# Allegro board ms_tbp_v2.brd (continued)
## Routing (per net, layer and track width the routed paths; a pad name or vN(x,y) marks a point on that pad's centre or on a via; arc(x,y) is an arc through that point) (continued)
SAS_B2_TX7P: length 15.2
  LYR6 w0.112: J23.G5 387.78,13.07 arc(387.92,13.42) 388.27,13.56 388.41,13.56 arc(388.78,13.72) 388.93,14.08 388.93,17.99 arc(388.96,18.06) 389.03,18.08 arc(389.12,18.12) 389.16,18.22 389.16,18.64 arc(389.12,18.75) 389.01,18.79 arc(388.95,18.82) 388.93,18.87 388.93,19.44 388.97,19.48 388.97,19.95 388.93,19.99 388.93,20.47 arc(388.86,20.81) 388.67,21.09 387.38,22.39 arc(387.2,22.65) 387.14,22.96 387.14,23.1 arc(387.05,23.55) 386.8,23.93 386.58,24.14 arc(386.36,24.48) 386.28,24.88 386.28,24.9 arc(386.3,25.03) 386.37,25.14 386.66,25.42 arc(386.67,25.43) 386.68,25.44 386.72,25.46 arc(386.8,25.47) 386.87,25.41 J24.2D7
SAS_B2_TX8N: length 22.5
  LYR6 w0.112: J24.2C8 386.6,29.71 arc(386.61,29.63) 386.56,29.56 386.09,29.09 arc(385.84,28.93) 385.55,28.87 385.16,28.87 arc(384.56,28.62) 384.31,28.02 384.31,26.84 384.31,22.5 arc(384.46,21.73) 384.9,21.08 386.15,19.83 arc(386.48,19.33) 386.6,18.75 386.6,17.09 386.6,11.21 arc(386.54,11.07) 386.39,11.01 386.31,11.01 arc(385.93,11.17) J23.F6
SAS_B2_TX8P: length 23
  LYR6 w0.112: J24.2C7 386.87,29.21 arc(386.8,29.27) 386.72,29.26 386.73,29.25 386.33,28.85 arc(385.97,28.61) 385.55,28.52 385.16,28.52 arc(384.8,28.38) 384.65,28.02 384.65,26.84 384.65,22.5 arc(384.78,21.86) 385.14,21.32 386.39,20.07 arc(386.8,19.47) 386.94,18.75 386.94,18.11 386.98,18.06 386.98,17.61 386.94,17.56 386.94,17.09 arc(386.97,17.02) 387.04,16.99 arc(387.13,16.95) 387.17,16.86 387.17,16.49 arc(387.12,16.38) 387.02,16.34 arc(386.96,16.32) 386.94,16.26 386.94,11.21 arc(386.78,10.83) 386.39,10.67 386.26,10.67 arc(386.14,10.64) 386.03,10.57 385.91,10.45 arc(385.81,10.31) J23.E6
SERIAL_B1_RX1: length 221.1
  TOP w0.102: v1(163.97,18.69) 164.14,18.86 168.68,18.86 169.93,17.61 169.93,6.89 J11.B3 ; U1.S2 7.3,45.76 10.6,42.45 10.6,35.27 10.06,34.73 10.06,34.2 10.29,33.97 v1(11.41,33.97)
  LYR3 w0.13: v1(53.65,31.2) 53.25,31.2 49.55,34.89 13.78,34.89 12.86,33.97 v1(11.41,33.97)
  BOTTOM w0.102: J7.G3 125.33,13.95 125.33,16.32 125,16.65 125,18.78 126.4,20.18 ; 126.4,20.18 126.4,20.92 125.74,21.58 120.12,21.58 116.29,25.41 101.33,25.41 100.23,26.51 100.23,26.51 99.62,27.12 95.57,27.12 95.08,26.63 86.32,26.63 80.25,32.7 56.47,32.7 54.97,31.2 v1(53.65,31.2) ; 126.4,20.18 128.3,20.18 130.74,22.62 130.74,26.25 131.78,27.29 133.46,27.29 135.77,24.98 143.72,24.98 146.01,22.69 157.03,22.69 158.94,20.79 158.94,17.2 159.75,16.38 161.66,16.38 v1(163.97,18.69)
SERIAL_B1_RX2: length 172.7
  TOP w0.102: U1.S6 2.22,47.59 6.64,43.17 6.64,42.86 9.35,40.15 9.35,35.6 8.94,35.19 8.94,32.63 9.73,31.84 11.36,31.84 v1(11.39,31.81) ; v1(123.73,20.84) 121.5,18.61 121.5,13.86 122.41,12.94 J7.G4
  LYR3 w0.13: v1(11.39,31.81) 12.67,31.81 14.62,33.77 37.98,33.77 41.92,29.83 51.77,29.83 52.48,29.12 v1(53.63,29.12)
  LYR4 w0.13: J1.I8 14.89,16.95 14.89,24.96 11.39,28.46 v1(11.39,31.81)
  BOTTOM w0.102: v1(123.73,20.84) 118.93,20.84 115.88,23.89 89.72,23.89 88.88,24.73 86.49,24.73 79.76,31.46 57.72,31.46 55.38,29.12 v1(53.63,29.12)
SERIAL_B1_TX1: length 220
  TOP w0.102: U1.S1 8.57,45.12 10.9,42.79 10.9,35.16 10.57,34.84 v1(10.57,34.48) ; J11.A3 170.73,4.64 169.62,5.75 169.62,17.45 169.59,17.48 168.83,18.24 163.37,18.24 v1(162.84,18.77) ; v1(127.82,20.76) 127.52,20.76 123.81,17.06 123.81,15.05 J7.H3
  LYR3 w0.13: v1(54.39,31.76) 53.32,31.76 49.91,35.18 13.5,35.18 12.81,34.48 v1(10.57,34.48)
  BOTTOM w0.102: v1(162.84,18.77) 160.77,16.7 159.82,16.7 159.3,17.22 159.3,20.93 157.16,23.08 146.13,23.08 143.85,25.36 136.02,25.36 133.76,27.62 131.68,27.62 130.36,26.3 130.36,22.75 129.39,21.78 128.84,21.78 v1(127.82,20.76) 126.75,21.83 120.27,21.83 116.44,25.67 101.48,25.67 99.76,27.38 95.19,27.38 94.82,27.01 89.85,27.01 89.72,26.89 86.44,26.89 80.3,33.03 56.37,33.03 55.1,31.76 v1(54.39,31.76)
SERIAL_B1_TX2: length 197.5
  TOP w0.102: v1(10.57,32.37) 9.81,32.37 9.23,32.96 9.23,35.1 9.65,35.52 9.65,40.41 7.78,42.28 7.78,43.4 3.49,47.69 U1.S5 ; J7.H4 122.42,14.35 123.27,15.2 123.27,17.31 125.2,19.24 v1(125.2,20.89)
  LYR3 w0.13: v1(10.57,32.37) 12.73,32.37 14.41,34.05 38.82,34.05 41.74,31.13 51.29,31.13 52.81,29.6 v1(54.41,29.6)
  LYR4 w0.13: J1.H8 15.02,13.46 15.02,3.87 14.65,3.51 13.39,3.51 13.11,3.78 13.11,25.74 9.56,29.3 9.56,31.94 9.99,32.37 v1(10.57,32.37)
  BOTTOM w0.102: v1(125.2,20.89) 124.56,20.89 124.32,21.31 118.89,21.31 115.96,24.24 89.8,24.24 88.68,25.36 86.32,25.36 79.92,31.76 57.51,31.76 55.35,29.6 v1(54.41,29.6)
SERIAL_B2_RX1: length 467.6
  TOP w0.102: J23.B3 390.93,6.89 390.93,17.61 389.85,18.69 384.68,18.69 v1(384.13,19.24)
  LYR3 w0.13: v1(7.3,42.99) 7.73,42.99 9.3,41.41 9.3,40.83 13.55,36.59 51.5,36.59 v1(53.78,34.3)
  BOTTOM w0.102: 346.31,19.9 346.31,13.24 346.11,13.04 J19.G3 ; 346.31,19.9 346.31,20.6 345.27,21.64 342.71,21.64 340.51,23.84 321.7,23.84 318.35,27.18 316.12,27.18 315.78,27.52 314.13,27.52 313.75,27.14 312.15,27.14 311.51,27.77 311.51,46.95 306.23,52.24 268.08,52.24 267.34,52.97 97.13,52.97 79.33,35.17 55.89,35.17 54.97,34.25 53.83,34.25 v1(53.78,34.3) ; 346.31,19.9 346.92,19.29 351.24,19.29 351.98,20.03 351.98,26.5 352.71,27.24 354.01,27.24 356.27,24.98 364.01,24.98 366.35,22.64 377.53,22.64 379.56,20.61 379.56,16.55 380.58,15.53 382.33,15.53 384.49,17.69 384.49,18.45 384.13,18.81 v1(384.13,19.24) ; v1(7.3,42.99) U1.S11
SERIAL_B2_RX2: length 523.9
  TOP w0.102: J19.G4 342.45,13.91 342.45,15.94 340.77,17.61 v1(340.77,21.17)
  LYR3 w0.13: v1(2.22,43.07) 3.75,41.53 6.85,41.53 12.92,35.46 50.11,35.46 53.25,32.32 v1(53.7,32.32)
  LYR6 w0.13: v1(340.77,21.17) 339.61,21.17 338.11,22.67 334.59,22.67 327.74,15.83 323.14,15.83 318.9,11.59 318.9,8.13 319.3,7.74 319.3,5.62 317.12,3.44 274.76,3.44 273.84,4.36 v1(272.3,4.36)
  BOTTOM w0.102: J13.I8 237.04,15.84 237.85,15.02 237.85,4.1 238.27,3.68 262.33,3.68 264.45,5.8 267.72,5.8 269.17,4.36 v1(272.3,4.36) ; v1(340.77,21.17) 340.29,21.17 338.82,22.64 328.73,22.64 328.43,22.34 311.67,22.34 305.8,28.21 305.8,29.53 306.18,29.91 306.18,46.6 303.68,49.1 268.83,49.1 265.97,51.96 97.75,51.96 85.78,39.98 85.78,38.93 80.23,33.37 56.1,33.37 55.05,32.32 v1(53.7,32.32) ; v1(2.22,43.07) U1.S7
SERIAL_B2_TX1: length 464.9
  TOP w0.102: v1(383.75,18.24) 383.86,18.35 389.72,18.35 390.12,17.95 390.62,17.45 390.62,5.8 J23.A3
  LYR3 w0.13: v1(347.17,21.17) 347.17,20.64 344.69,18.15 344.69,15.17 J19.H3 ; v1(8.57,42.96) 9.63,41.9 9.63,40.91 13.67,36.87 51.87,36.87 53.96,34.79 v1(54.49,34.79)
  BOTTOM w0.102: v1(8.57,42.96) U1.S12 ; v1(54.49,34.79) 54.54,34.73 54.8,34.73 55.48,35.42 79.15,35.42 96.96,53.23 267.6,53.23 268.28,52.54 306.61,52.54 311.92,47.23 311.92,27.88 312.4,27.39 313.24,27.39 313.75,27.9 315.78,27.9 316.16,27.52 318.75,27.52 322.13,24.14 340.7,24.14 342.92,21.92 346.35,21.92 347.1,21.17 v1(347.17,21.17) 347.17,21.15 348.55,19.77 351.09,19.77 351.62,20.31 351.62,26.73 352.61,27.72 354.11,27.72 356.32,25.51 364.42,25.51 366.81,23.13 378.09,23.13 380.19,21.02 380.19,16.95 380.73,16.42 381.93,16.42 v1(383.75,18.24)
SERIAL_B2_TX2: length 523.6
  TOP w0.102: J19.H4 343.75,14.34 344.41,15 344.41,18.83 v1(342.07,21.17)
  LYR3 w0.13: v1(54.46,32.8) 53.27,32.8 50.33,35.74 13.15,35.74 7.04,41.85 4.68,41.85 v1(3.49,43.04)
  LYR6 w0.13: J13.H8 238.01,13.43 238.01,4.09 238.48,3.62 262.55,3.62 264.57,5.63 273.53,5.63 275.19,3.98 317.17,3.98 318.92,5.73 318.92,7.21 318.43,7.71 318.43,11.69 320.14,13.41 320.14,13.81 322.7,16.37 327.64,16.37 334.42,23.15 339.71,23.15 341.69,21.17 v1(342.07,21.17)
  BOTTOM w0.102: v1(54.46,32.8) 54.49,32.83 55.05,32.83 55.87,33.65 80,33.65 85.5,39.15 85.5,40.11 97.6,52.21 266.25,52.21 267.77,50.69 303.82,50.69 307.7,46.8 307.7,42.41 306.84,41.54 306.84,29.88 307.6,29.12 307.6,28.49 307.93,28.16 307.93,27.27 312.55,22.65 328,22.65 328.38,23.03 339.91,23.03 341.76,21.17 v1(342.07,21.17) ; U1.S8 v1(3.49,43.04)
SKU_B1_ID0: length 35.9
  TOP w0.102: v1(124.65,40.22) R3.1 R2.2
  LYR3 w0.13: J7.F3 124.42,11.65 125.28,12.51 125.28,16.01 124.75,16.55 124.75,19.57 126.12,20.94 126.12,23.67 128.28,25.83 128.28,34.99 125.38,37.88 124.18,37.88 123.8,38.27 123.8,39.37 v1(124.65,40.22)
SKU_B1_ID1: length 33.1
  TOP w0.102: v1(123.04,41.16) 123.02,41.14 R5.1 R4.2
  LYR3 w0.13: J7.I4 122.42,16.1 123.15,16.83 123.15,18.35 120.58,20.92 120.58,24.27 118.57,26.28 118.57,34.53 121.27,37.22 122.97,37.22 123.49,37.75 123.49,40.71 v1(123.04,41.16)
SKU_B1_ID2: length 58.8
  TOP w0.102: R75.1 R6.2 R7.1 91.64,28.65 v1(91.65,28.64)
  LYR3 w0.13: v1(129.29,23.81) 129.95,23.15 129.95,21.78 129.12,20.94 129.12,19.37 127.44,17.69 127.44,12.51 126.47,11.54 J7.F2
  BOTTOM w0.102: v1(129.29,23.81) 127.88,22.4 120.58,22.4 116.75,26.23 101.94,26.23 100.21,27.95 92.79,27.95 92.11,28.64 v1(91.65,28.64)
SKU_B2_ID0: length 39
  TOP w0.102: R31.1 R30.2 343.03,43.62 v1(343.87,43.62)
  LYR3 w0.13: J19.F3 345.42,11.65 346.21,12.44 346.21,18.63 347.96,20.38 347.96,24.45 349.74,26.23 349.74,34.33 345.93,38.14 344.89,38.14 344.63,38.4 344.63,42.87 v1(343.87,43.62)
SKU_B2_ID1: length 32.4
  TOP w0.102: v1(344.1,40.75) R33.1 R32.2
  LYR3 w0.13: J19.I4 344.18,16.5 344.18,21.17 339.61,25.74 339.61,33.69 342.73,36.82 343.64,36.82 344.43,37.6 344.43,38.16 344.1,38.49 v1(344.1,40.75)
SKU_B2_ID2: length 55.8
  TOP w0.102: R61.1 R34.2 R35.1 v1(313.27,29.78)
  LYR3 w0.13: J19.F2 348.6,12.72 348.6,16.07 350.76,18.22 v1(350.76,21.12)
  BOTTOM w0.102: v1(350.76,21.12) 350.07,21.81 348.67,21.81 348.02,22.46 343.24,22.46 340.8,24.9 322.66,24.9 317.79,29.78 v1(313.27,29.78)
UNNAMED_4_1X2HDR_I81_IO: length 3.4
  TOP w0.305: R9.1 89.44,45.72 J25.2
UNNAMED_4_1X2HDR_I90_IO: length 3.7
  TOP w0.305: J26.2 81.62,45.93 R11.1
UNNAMED_4_FERRITE_I148_A: length 1.5
  TOP w0.305: FB1.1 v1(136.79,4.28) 136.76,4.31 FS1.2
UNNAMED_4_FERRITE_I151_B: length 1.8
  TOP w0.305: FB2.2 144.16,4.37 v1(144.18,4.38) 144.2,4.36 FS2.1
UNNAMED_6_1X2HDR_I52_IO: length 3.4
  TOP w0.305: R37.1 310.44,45.72 J28.2
UNNAMED_6_1X2HDR_I56_IO: length 3.7
  TOP w0.305: J29.2 298.92,45.94 R39.1
UNNAMED_6_FERRITE_I24_A: length 1.6
  TOP w0.305: FB3.1 v1(357.74,4.28) FS3.2
UNNAMED_6_FERRITE_I27_B: length 1.8
  TOP w0.305: 365.21,4.31 FS4.1 ; 365.21,4.31 364.37,4.31 FB4.2 ; 365.21,4.31 v1(365.21,4.33)
UNNAMED_8_FERRITE_I47_B: length 1.4
  TOP w0.305: 376.79,38.94 377.46,38.94 FS7.1 ; 376.79,38.94 v1(376.79,38.95) ; 376.79,38.94 FB7.2
UNNAMED_8_FERRITE_I51_A: length 1.4
  TOP w0.305: FS5.2 377.66,43.1 v1(377.67,43.09) FB5.1
UNNAMED_8_FERRITE_I54_A: length 1.4
  TOP w0.305: FS6.2 377.96,50.25 377.96,49.57 v1(377.98,49.54) 377.96,49.52 FB6.1
UNNAMED_16_FERRITE_I40_A: length 1.4
  TOP w0.381: FS9.2 156.47,49.34 v1(156.45,49.31) 156.47,49.29 FB9.1
UNNAMED_16_FERRITE_I46_B: length 1.6
  TOP w0.305: FB10.2 155.44,38.81 v1(155.46,38.8) 155.48,38.83 FS10.1
UNNAMED_16_FERRITE_I115_A: length 1.6
  TOP w0.305: FB8.1 156.47,43.3 v1(156.45,43.32) FS8.2
USB_B1_N: length 25
  BOTTOM w0.127: J1.C10 11.45,6.89 10.83,6.89 10.52,7.2 10.52,7.43 10.11,7.84 9.89,7.84 9.61,8.12 9.61,8.87 9.79,9.05 9.79,9.58 9.61,9.76 9.61,10.02 7.25,12.38 7.25,13.61 7.42,13.79 7.42,14.22 7.25,14.4 7.25,14.87 6.16,15.96 6.16,16.19 5.83,16.52 5.6,16.52 5.19,16.93 4.9,16.93 4.72,17.11 4.34,17.11 4.16,16.93 3.66,16.93 3.49,17.11 3.06,17.11 2.88,16.93 2.65,16.93 1.4,18.17 1.4,20.23 1.58,20.41 1.58,20.89 1.4,21.07 1.4,21.3 2.09,21.99 2.77,21.99 U2.2
USB_B1_P: length 25
  BOTTOM w0.127: U2.3 2.77,22.29 1.97,22.29 1.1,21.42 1.1,18.05 2.52,16.62 5.06,16.62 6.94,14.74 6.94,12.26 9.3,9.89 9.3,7.99 10.71,6.59 11.45,6.59 J1.B10
USB_B2_N: length 23.9
  BOTTOM w0.127: U3.2 220.01,11.74 219.17,11.74 218.19,10.76 218.19,10.53 218.37,10.35 218.37,9.92 218.19,9.74 218.19,9.31 218.37,9.13 218.37,8.7 218.19,8.52 218.19,7.43 218.45,7.17 218.68,7.17 218.99,6.86 218.99,6.63 219.77,5.85 220.11,5.85 220.29,6.03 220.72,6.03 220.9,5.85 221.33,5.85 221.51,6.03 221.94,6.03 222.12,5.85 222.55,5.85 222.73,6.03 223.16,6.03 223.34,5.85 223.77,5.85 223.95,6.03 224.38,6.03 224.56,5.85 228.61,5.85 229.65,6.89 232.45,6.89 J13.C10
USB_B2_P: length 23.9
  BOTTOM w0.127: U3.3 220.01,12.04 219.05,12.04 217.89,10.88 217.89,7.3 219.64,5.55 228.73,5.55 229.77,6.59 232.45,6.59 J13.B10

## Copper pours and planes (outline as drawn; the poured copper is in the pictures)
GND on TOP: 252.61,11.81 260.93,10.64 252.61,9.48
GND on TOP: 318.7,3.22 318.43,3.32 318.14,3.35 274.38,3.35 274.38,34.38 273.36,35.39 240.34,35.39 231.96,27.01 231.96,4.41 230.91,3.35 147.47,3.35 147.47,5 147.45,5.02 143.19,5.02 143.19,8.72 137.47,8.72 137.47,4.9 133.78,4.9 133.78,3.35 117.39,3.35 117.39,15.98 114.91,15.98 114.91,15.96 111.11,15.96 111.11,16.89 111.1,16.9 108.14,16.9 108.14,15.96 95.82,15.96 95.82,23.71 90.61,28.92 87.9,28.92 86.8,30.02 86.8,54.03 423.84,54.03 425.39,53.39 426.03,51.84 426.03,15.5 426.36,14.63 427.19,14.2 427.19,5.54 426.55,3.99 425,3.35 398.11,3.35 397.57,3.9 397.57,16.22 395.66,18.12 384.87,18.12 383.73,16.98 383.73,3.99 383.09,3.35 338.13,3.35 338.13,16.09 325.12,16.09 325.12,16.87 324.15,17.83 323.88,17.83 323.58,17.54 323.58,17.12 323.59,17.12 323.59,16.09 318.7,16.09 ; 8 cut-outs
GND on TOP: 31.48,44.96 31.48,54.35 31.49,54.34 51.05,54.34 51.05,44.35 50.63,43.93 32.5,43.93
GND on BOTTOM: 94.98,22.44 94.98,3.14 52.69,3.14 52.69,27.39 53.58,28.28 56.07,28.28 58.76,30.98 79.38,30.98 87.1,23.25 94.17,23.25
GND on BOTTOM: 31.48,54.29 31.48,44.82 32.19,44.11 50.73,44.11 51.04,44.41 51.04,54.29
GND on BOTTOM: 316.87,53.89 316.87,30.82 316.95,30.82 317.43,30.34 318.65,30.34 323.17,25.82 350.27,25.82 350.4,25.95 350.4,27.67 352.3,29.58 354.31,29.58 356.75,27.14 369.2,27.14 369.2,53.89
GND on LYR2: 98.19,0.56 98.19,2.04 97.88,2.79 97.13,3.1 1.5,3.1 0.83,3.37 0.56,4.04 0.56,54.11 0.8,54.35 9.65,54.35 9.89,54.11 9.89,45.19 10.8,44.28 11.71,45.19 11.71,54.11 11.94,54.34 51.29,54.34 51.52,54.11 51.52,46.34 52.12,44.88 53.58,44.28 54.58,44.28 56.04,44.88 56.64,46.34 56.64,52.34 57.21,53.71 58.58,54.28 423.84,54.28 425.57,53.57 426.28,51.84 426.28,15.5 426.59,14.75 427.34,14.44 427.44,14.44 427.44,5.54 426.73,3.81 425,3.1 337.28,3.1 336.54,2.79 336.23,2.04 336.23,0.56 319.19,0.56 319.19,2.04 318.88,2.79 318.13,3.1 192.64,3.1 192.59,3.05 115.92,3.05 115.9,3.03 115.41,2.64 115.23,2.04 115.23,0.56
GND on LYR3: 161.6,3.52 161.6,54.18 161.61,54.19 305.87,54.19 305.87,28.03 309.94,23.96 313.88,23.96 315.27,22.57 315.27,4.03 302.19,4.03 302.06,3.9 274,3.9 274,31.97 269.78,36.18 269.78,36.21 240.8,36.21 239.99,35.39 239.99,35.37 230.94,26.33 230.94,3.52
GND on LYR4: 381.41,3.14 381.41,53.81 384.52,53.81 384.55,53.78 406.53,53.78 406.53,3.14
GND on LYR5: 317.28,3.11 317.28,23.91 317.35,23.91 317.23,24.04 317.23,53.81 424.75,53.81 426.14,52.41 426.14,14.82 427.29,13.68 427.29,4.79 426.09,3.59 420.55,3.14 336.91,3.14 336.24,2.46 336.24,2.4 334.4,0.56 321.54,0.56 318.98,3.12
GND on LYR5: 272.73,30.8 264.45,30.8 264.22,30.57 264.22,28.92 263.96,28.66 262.95,28.66 258.2,33.41 240.98,33.41 233.84,26.28 233.84,4.41 234.4,3.85 272.24,3.85 272.73,4.33
GND on LYR5: 13.16,33.69 48.34,33.69 49.69,32.35 50.78,32.35 52.2,30.92 52.2,4 51.86,3.66 41.5,3.66 41.49,3.64 13.6,3.64 13.55,3.59 9.63,3.59 9.51,3.72 9.51,11.87 7.83,13.55 1.66,13.55 1.66,27.75 1.89,27.98 6.08,27.98 6.1,28 7.47,28
GND on LYR5: 97.9,3.01 97.9,11.04 103.78,16.92 108.7,16.92 111.88,20.09 116.34,20.09 118.55,22.3 159.95,22.3 159.97,37.06 159.97,37.63 161.66,39.33 162.24,39.91 182.99,39.91 184.44,38.47 184.44,38.49 185.05,37.88 185.05,3.16 185.02,3.19 160,3.19 160,22.29 130.84,22.29 130.84,3.24 159.57,3.24 159.57,3.19 115.81,3.19 113.18,0.56 100.35,0.56
GND on LYR7: 98.19,0.56 98.19,2.04 97.88,2.79 97.13,3.1 1.5,3.1 0.83,3.37 0.56,4.04 0.56,54.11 0.79,54.34 9.66,54.34 9.89,54.11 9.89,45.19 10.8,44.28 11.71,45.19 11.71,54.11 11.94,54.34 51.29,54.34 51.52,54.11 51.52,46.34 52.12,44.88 53.58,44.28 54.58,44.28 56.04,44.88 56.64,46.34 56.64,52.34 57.21,53.71 58.58,54.28 423.84,54.28 425.57,53.57 426.28,51.84 426.28,15.5 426.59,14.75 427.34,14.44 427.44,14.44 427.44,5.54 426.73,3.81 425,3.1 337.28,3.1 336.54,2.79 336.23,2.04 336.23,0.56 319.19,0.56 319.19,2.04 318.88,2.79 318.13,3.1 192.64,3.1 192.59,3.05 115.92,3.05 115.9,3.03 115.41,2.64 115.23,2.04 115.23,0.56
P3V3_10G_B1_VCCR on TOP (solid shape): 140.05,7.99 140.05,5.43 138.97,5.43 138.98,4.79 138.72,4.53 138.72,4.03 138.04,4.03 138.04,8.3 139.74,8.3
P3V3_10G_B1_VCCR on TOP: 139.26,13.83 139.77,13.83 139.77,17.37 139.61,17.53 139.17,17.53 139,17.36 139,16.11 139.26,15.84
P3V3_10G_B1_VCCT on TOP (solid shape): 142.65,4.03 141.9,4.03 141.9,4.79 141.26,5.42 140.64,5.42 140.64,7.98 140.95,8.29 142.65,8.29
P3V3_10G_B1_VCCT on TOP: 140.55,13.84 140.05,13.84 140.05,17.38 140.21,17.54 140.59,17.54 140.77,17.36 140.77,16.07 140.55,15.85
P3V3_10G_B2_VCCR on TOP (solid shape): 361.05,7.99 361.05,5.43 359.97,5.43 359.98,4.79 359.72,4.53 359.72,4.03 359.04,4.03 359.04,8.3 360.74,8.3
P3V3_10G_B2_VCCR on TOP: 360.26,13.83 360.76,13.83 360.76,17.38 360.61,17.53 360.14,17.53 360,17.39 360,16.11 360.26,15.85
P3V3_10G_B2_VCCT on TOP (solid shape): 363.65,4.03 362.9,4.03 362.9,4.79 362.26,5.42 361.64,5.42 361.64,7.98 361.95,8.29 363.65,8.29
P3V3_10G_B2_VCCT on TOP: 361.56,13.83 361.06,13.83 361.06,17.38 361.22,17.54 361.58,17.54 361.8,17.31 361.8,16.09 361.56,15.85
P3V3_40G_B1_VCC1 on TOP: 151.95,36.92 153.6,36.92 154.13,37.45 154.13,37.88 154.44,38.19 155.15,38.19 155.33,38.01 155.33,35.27 155.05,34.99 152.43,34.99 151.95,35.47
P3V3_40G_B1_VCC_RX on TOP: 106.19,8.66 105.83,8.66 105.83,10.61 105.54,10.9 105.54,11.16 105.77,11.39 106.26,11.39 106.26,10.69 106.19,10.63
P3V3_40G_B1_VCC_RX on TOP: 152.29,50.09 154.49,50.09 155.09,49.49 155.51,49.49 155.87,49.12 155.87,48.16 156,48.03 156,47.05 154.77,47.05 154.58,47.24 152.2,47.24 152.08,47.37 152.08,49.87
P3V3_40G_B1_VCC_TX on TOP: 152.2,43.99 154.11,43.99 155.3,42.8 155.85,42.8 155.85,42.06 155.98,41.94 155.98,40.96 154.74,40.96 154.55,41.15 152.2,41.15 152.05,41.3 152.05,43.84
P3V3_40G_B2_VCC1 on TOP: 373.33,37.05 374.98,37.05 375.52,37.58 375.52,38.01 375.82,38.32 376.53,38.32 376.71,38.14 376.71,35.39 376.43,35.12 373.81,35.12 373.33,35.6
P3V3_40G_B2_VCC_RX on TOP: 373.46,50.09 376.29,50.09 377.26,49.12 377.26,48.16 377.38,48.03 377.38,47.05 376.15,47.05 375.96,47.24 373.46,47.24
P3V3_40G_B2_VCC_TX on TOP: 373.43,43.87 376.26,43.87 377.23,42.9 377.23,41.94 377.36,41.81 377.36,40.83 376.13,40.83 375.93,41.02 373.43,41.02
P3V3_B1_QSFP on BOTTOM: 136.61,26.25 134.49,28.37 130.93,28.37 130.07,27.51 127.1,30.49 127.1,32.6 118.86,32.6 118.86,30.73 114.64,26.5 90.48,26.5 89.9,27.09 92.13,27.09 92.13,28.92 88.07,28.92 86.29,30.7 86.29,39.97 97.8,51.47 162.54,51.47 163.38,50.63 163.38,42 155.76,34.38 154.24,34.38 151.87,32.02 151.87,26.78 151.34,26.25
P3V3_B1_QSFP on LYR4: 117.41,3.26 117.41,18.25 117.79,18.63 130.08,18.63 131.15,17.56 131.15,11.77 133.94,8.98 148.47,8.98 148.47,3.26
P3V3_B1_QSFP on LYR6: 133.55,5.96 145.6,5.96 145.6,22.8 141.79,26.61 141.79,27.8 142.45,28.46 151.67,28.46 152.08,28.05 152.08,3.05 133.54,3.05 133.55,3.06
P3V3_B2_QSFP on LYR4: 338.77,3.42 338.77,18.02 352.38,18.02 352.38,9.46 373.18,9.46 373.18,3.42
P3V3_B2_QSFP on LYR6: 368.38,3.39 368.38,5.63 368.97,6.21 368.97,24.93 368.92,24.88 355.68,38.11 348.27,38.11 346.56,39.81 341.69,39.81 338.79,36.92 327.34,36.92 320.73,30.31 309.91,30.31 308.02,32.21 308.02,39.7 310.19,41.87 318.45,41.87 319.97,43.4 319.97,52.67 320,52.69 378.72,52.69 380.47,50.94 380.47,36.13 373.54,36.13 373.2,35.79 373.2,3.39
P5V_USB_B1 on BOTTOM: 6.36,17.77 8.64,15.48 8.64,11.95 11.06,9.54 12.55,9.54 13.06,10.05 13.06,10.58 12.55,11.09 11.44,11.09 10.75,11.77 10.75,17.92 8.21,20.46 2.67,20.46 2.24,20.03 2.24,18.4 2.88,17.77
P5V_USB_B2 on BOTTOM: 222.61,10.86 233.51,10.86 233.84,10.53 233.84,9.87 233.43,9.46 231.22,9.46 229.14,7.38 219.64,7.38 219.34,7.68 219.34,9.87 219.72,10.25 222,10.25
P12V on TOP: 53.23,3.3 52.76,3.77 52.76,32.83 50.6,34.99 11.82,34.99 11.26,35.55 11.26,44.46 11.55,44.78 11.66,45.19 11.66,54.13 11.87,54.34 30.76,54.34 30.76,45.53 30.77,45.53 30.77,44.67 31.99,43.45 50.91,43.45 51.49,44.03 55.56,44.03 56.89,45.37 56.89,52.34 57.39,53.53 58.58,54.03 85.78,54.03 85.78,29.3 86.55,28.54 90.36,28.54 95.38,23.51 95.38,3.89 94.8,3.3 ; 4 cut-outs
P12V on BOTTOM: 274.38,34.38 273.24,35.52 240.47,35.52 231.92,26.97 231.92,14.22 231.54,13.84 219.55,13.84 216.06,10.35 216.06,3.95 215.93,3.82 186.11,3.82 186.11,37.66 180.8,42.96 180.78,42.94 167.24,42.94 167.22,42.96 167.22,51.4 264.6,51.4 267.77,48.22 291.27,48.22 304.22,35.27 304.22,28.04 310.83,21.44 315.56,21.44 316.16,20.84 316.16,3.16 316.11,3.11 274.38,3.11 ; 1 cut-out
P12V on BOTTOM: 11.82,34.99 11.26,35.55 11.26,44.21 11.69,44.64 11.69,54.17 11.87,54.34 30.76,54.34 30.76,44.67 31.78,43.65 51.11,43.65 51.62,44.16 55.5,44.16 56.89,45.55 56.89,52.34 57.39,53.53 58.58,54.03 95.78,54.03 77.74,35.99 54.35,35.99 53.35,34.99
P12V on LYR3: 53.12,3.28 53.14,3.3 52.78,3.3 52.76,3.31 52.76,27.14 54.52,28.89 54.52,28.92 55.25,29.65 55.25,34.94 52.99,37.2 14.28,37.2 10.64,40.84 10.64,44.29 11.39,44.49 11.71,45.19 11.71,54.11 11.94,54.34 51.29,54.34 51.52,54.11 51.52,46.34 52.12,44.88 53.58,44.28 54.58,44.28 56.04,44.88 56.64,46.34 56.64,52.34 57.21,53.71 58.58,54.28 85.44,54.28 85.78,53.94 85.78,29.33 86.93,28.19 86.93,27.01 86.45,26.54 86.45,25.62 87.09,24.98 91.17,24.98 94.85,21.3 94.85,4.36 93.77,3.28
P12V on LYR4: 52.76,3.34 52.76,31.1 50.12,33.74 12.43,33.74 9.57,36.6 9.57,42.11 9.58,42.13 9.58,43.14 10.73,44.28 11.42,44.52 11.71,45.19 11.71,54.11 11.94,54.34 51.29,54.34 51.52,54.11 51.52,46.34 52.12,44.88 53.58,44.28 54.58,44.28 56.04,44.88 56.64,46.34 56.64,52.34 57.21,53.71 58.58,54.28 334.32,54.28 334.91,53.69 334.91,33.01 325.85,23.95 325.85,23.04 316.87,14.06 316.87,4.66 316.49,4.28 273.77,4.28 273.77,32.25 271,35.01 261.45,35.01 258.02,31.58 242.83,31.58 238.11,26.86 231.71,26.86 231.71,4 149.33,4 149.21,4.13 149.21,10.02 149.18,10.02 149.18,21.03 133.91,21.03 133.91,21.07 133.56,21.07 133.56,21.33 131.59,21.33 131.59,19.57 131.58,19.57 131.58,19.56 117.03,19.56 116.16,18.69 116.16,18.68 116.16,12.88 100.63,12.88 99.38,11.63 99.38,11.61 98.09,11.61 98.08,11.59 98.08,7.25 96.77,7.25 96.77,3.34 ; 8 cut-outs
P12V on LYR5: 293.43,3.07 274.15,3.11 273.77,3.11 273.77,3.11 273.77,32.24 268.43,37.57 229.67,37.59 228.51,36.43 228.51,4.52 227.92,3.92 186.34,3.92 186.25,4.01 186.25,38.1 183.73,40.63 161.79,40.63 161.69,40.53 161.69,40.52 159.09,37.92 159.09,26.78 157.33,25.03 120.2,25.03 115.49,20.32 111.63,20.32 108.56,17.25 103.38,17.25 97.3,11.18 97.3,3.86 96.53,3.09 52.74,3.09 52.75,3.1 52.75,31.34 51.24,32.85 49.84,32.85 48.52,34.18 10.35,34.18 9.44,35.08 9.44,38.46 6.81,41.08 0.53,41.08 0.53,54.12 0.76,54.34 9.69,54.34 9.92,54.12 9.92,45.19 10.8,44.31 11.68,45.19 11.68,54.12 11.9,54.34 51.33,54.34 51.33,54.34 51.55,54.12 51.55,46.34 52.14,44.9 53.58,44.31 54.58,44.31 56.02,44.9 56.61,46.34 56.61,52.34 57.19,53.73 58.58,54.31 316.49,54.31 316.49,3.07
P12V on LYR6: 52.92,3.09 52.92,31.18 51.11,32.98 49.84,32.98 48.06,34.76 40.83,34.76 38.41,37.17 10.98,37.17 9.46,38.7 9.46,43.11 10.64,44.29 11.39,44.49 11.71,45.19 11.71,54.11 11.94,54.34 51.29,54.34 51.52,54.11 51.52,46.34 52.12,44.88 53.58,44.28 54.58,44.28 56.04,44.88 56.64,46.34 56.64,52.34 57.21,53.71 58.58,54.28 317.3,54.28 317.3,42.91 316.92,42.53 309.86,42.53 307.07,39.74 307.07,32.27 309.51,29.83 309.51,29.81 317.28,29.81 317.28,30.01 317.3,30.01 317.3,4.15 316.29,3.14 278.32,3.14 275.01,6.44 275.01,32.47 272.47,35.01 239.83,35.01 232.06,27.24 232.04,27.24 231.76,26.96 231.76,4.36 231.38,3.98 185.99,3.98 185.82,4.14 185.82,37.66 183.77,39.71 170.3,39.71 170.3,39.91 165.61,39.91 165.61,39.97 164.71,39.97 164.71,39.7 164.71,39.69 164.85,39.69 164.85,39.69 160.28,39.69 155.68,35.09 131.43,35.09 131.43,33.59 125.23,27.39 113.62,27.39 98.71,12.48 96.76,12.48 96.76,3.89 95.95,3.09
P12V_MEZZ_B1 on LYR6: 9.46,15.07 8.44,16.09 8.44,31.46 8.95,31.97 8.95,34.76 10.98,36.79 38.03,36.79 40.7,34.12 45.22,34.12 45.37,33.97 45.37,31.36 45.35,31.33 43.37,31.33 42.73,30.7 42.73,28.99 42.7,28.97 40.65,28.97 35.62,34 19.62,34 12.76,27.14 12.76,15.07
P12V_MEZZ_B2 on LYR5: 240.52,33.92 258.25,33.92 263.18,28.99 263.66,28.99 263.84,29.17 263.84,30.95 263.96,31.08 266.38,31.08 266.52,31.22 266.52,36.64 266.12,37.05 230.06,37.05 229.37,36.36 229.37,15.07 233.46,15.07 233.46,26.86
(no net) on TOP: 359.04,4.03 359.04,8.3 359.04,8.3 360.74,8.3 361.05,7.99 361.05,5.43 359.97,5.43 359.98,4.79 359.72,4.53 359.72,4.03
(no net) on TOP: 138.04,4.03 138.04,8.3 138.04,8.3 139.74,8.3 140.05,7.99 140.05,5.43 138.97,5.43 138.98,4.79 138.72,4.53 138.72,4.03
(no net) on TOP: 363.65,4.03 363.65,8.29 363.66,8.29 361.95,8.29 361.64,7.98 361.64,5.42 362.26,5.42 362.9,4.79 362.9,4.03
(no net) on TOP: 142.65,4.03 142.65,8.29 142.66,8.29 140.95,8.29 140.64,7.98 140.64,5.42 141.26,5.42 141.9,4.79 141.9,4.03
Net_372 on LYR6 (solid shape): 200.52,2.54 192.9,2.54 192.9,3.05 200.52,3.05
Net_373 on TOP (solid shape): 195.44,2.54 192.9,2.54 192.9,3.05 195.44,3.05
Net_374 on LYR2 (solid shape): 196.45,2.54 192.9,2.54 192.9,3.05 196.45,3.05
Net_375 on LYR3 (solid shape): 197.47,2.54 192.9,2.54 192.9,3.05 197.47,3.05
Net_376 on LYR4 (solid shape): 198.49,2.54 192.9,2.54 192.9,3.05 198.49,3.05
Net_377 on LYR5 (solid shape): 199.5,2.54 192.9,2.54 192.9,3.05 199.5,3.05

Small or netless copper shapes (teardrops, artwork), in the pictures only: 2 on TOP, 6 on BOTTOM

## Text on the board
BOTTOM: X887571-005
TOP: X887571-005
Ref Des/Silkscreen Top: S/N Label | PCB Rev A
DIMENSION: 5 | (4x) | (2x) | (6x) | (3x) | BEVEL BOTH SIDES | AT GOLD FINGERS | SEE SECTION A:A | A | 19 | 12 | VIEW E-E | DETAIL A (6X) | SECTION A:A (2X)
User.19: SHAW
User.25: Initial Release | Change to Green Soldermask | 2/10/14 | 5/09/14 | A | B | MS PDM VER: A.1 | MS PART NO: X887571-005 | (N/A)
User.27: A | Initial Release | 10/1/13 | MS PDM VER: D.1 | MS PART NO: X887573-001
User.30: SOLDERMASK | +/- 5 MIL | 4.0 +/- 0.5 MIL | 0.5 +/- 0.1 MIL | TITLE: | MS PDM VER: A.1 | MS PART NO: X887571-005 | 85ohm +/- 10% | Fabrication Drawing | Tray Backplane PCB B (OSP)
User.37: FIGURE | SIZE | 10.000 | 14.000 | 15.000 | 20.000 | 24.000 | 30.000 | 33.000 | 38.000 | 40.000 | 41.000 | 55.000 | 87.000 | 138.000 | 156.000 | 50.000 | 61.000 | 63.000 | 86.000 | 125.000 | DRILL CHART: TOP to BOTTOM | ALL UNITS ARE IN MILS | TOLERANCE | +2.000/-10.000 | +3.000/-3.000 | +2.000/-2.000 | +5.000/-5.000 | +2.000/-1.000 | PLATED | NON-PLATED | QTY | 1600 | 48 | 144 | 538 | 20 | 2 | 18 | 8 | 44 | 4 | 6 | 3
